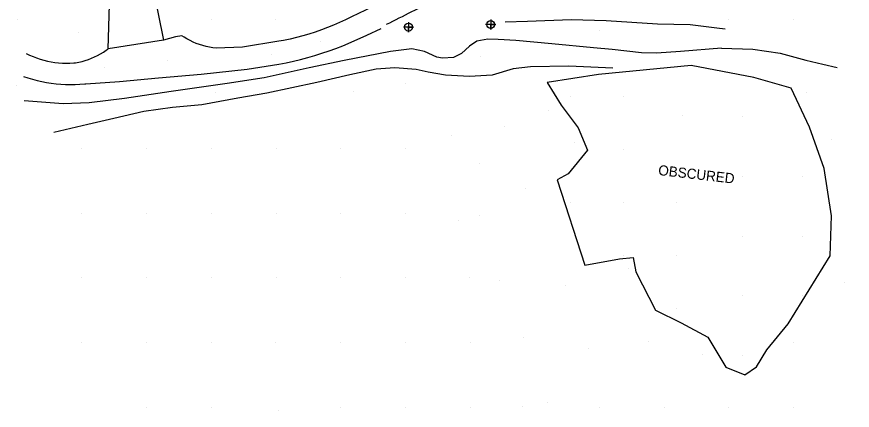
# Model space of a CAD drawing. Extents: x 524772 to 528246, y 273285 to 283088.
# Drawn here: x 526948.5 to 527074.5, y 276192.7 to 276252.1 of the extents above; entities that cross this region are included whole.
import ezdxf

# ---------------------------------------------------------------- set-up
doc = ezdxf.new("R2010")
doc.units = 0
for name, color, linetype in [('Exist DTM Regular Point CELL', 7, 'Continuous'), ('Exist Roads Soil', 7, 'Continuous'), ('PH Exist DTM Breakline', 7, 'Continuous'), ('PH Exist DTM Obscure Area', 7, 'Continuous'), ('PH Exist DTM Obscure Area Text', 7, 'Continuous'), ('PH Exist DTM Point', 7, 'Continuous')]:
    doc.layers.add(name, color=color, linetype=linetype)

# ---------------------------------------------------------------- blocks, each defined once
blk = doc.blocks.new('EXIST DTM REGULAR POINT')
at = {"layer": 'Exist DTM Regular Point CELL'}
blk.add_lwpolyline([(0, 0.00152), (0, -0.00152), (0, 0), (0.00152, 0), (-0.00152, 0)], dxfattribs=at)
blk.add_circle((0, 0), 0.00119, dxfattribs=at)

msp = doc.modelspace()

# ---------------------------------------------------------------- linework, layer by layer
at = {"layer": 'Exist Roads Soil'}
msp.add_spline([(527004.3, 276250.96), (527011.89, 276254.76), (527021.35, 276259.26), (527033.94, 276264.59), (527047.08, 276268.94), (527059.34, 276272.23), (527073.2, 276275.45), (527085.01, 276278.61), (527097.76, 276281.39), (527108, 276283.82), (527111.74, 276284.33), (527113.41, 276284.2), (527116.23, 276282.04), (527118.13, 276280.02)], degree=3, dxfattribs=at)
at = {"layer": 'PH Exist DTM Breakline'}
for points in [[(526969.04, 276256.57), (526970.63, 276248.58), (526962.29, 276247.27), (526962.49, 276253.93)], [(527002.18, 276253.59), (526998.98, 276252.07), (526998.09, 276251.64), (526997.2, 276251.22), (526996.29, 276250.83), (526995.38, 276250.46), (526994.46, 276250.12), (526993.53, 276249.79), (526992.59, 276249.49), (526991.64, 276249.22), (526990.69, 276248.96), (526989.73, 276248.73), (526988.77, 276248.53), (526988.05, 276248.39), (526982.57, 276247.53), (526978.59, 276247.37), (526978.08, 276247.43), (526977.57, 276247.51), (526977.07, 276247.62), (526976.57, 276247.75), (526976.08, 276247.9), (526975.59, 276248.08), (526975.11, 276248.28), (526974.65, 276248.5), (526974.19, 276248.75), (526973.75, 276249.01), (526973.42, 276249.23), (526972.47, 276249.05), (526970.63, 276248.58)], [(527022.18, 276251.31), (527025.54, 276251.42), (527032.13, 276251.69), (527037.41, 276251.52), (527045.17, 276251.03), (527050.08, 276250.92), (527054.11, 276250.42), (527055.36, 276250.29)], [(526949.52, 276243.1), (526950.2, 276242.87), (526950.89, 276242.66), (526951.59, 276242.47), (526952.3, 276242.32), (526953.01, 276242.18), (526953.72, 276242.07), (526954.44, 276241.98), (526955.16, 276241.92), (526955.88, 276241.88), (526956.6, 276241.86), (526957.32, 276241.87), (526958.05, 276241.9), (526958.77, 276241.96), (526958.92, 276241.98), (526964.02, 276242.33), (526969.9, 276242.87), (526976.31, 276243.41), (526983.27, 276244.21), (526988.04, 276244.92), (526989.13, 276245.14), (526990.23, 276245.38), (526991.32, 276245.65), (526992.4, 276245.94), (526993.48, 276246.25), (526994.55, 276246.58), (526995.61, 276246.94), (526996.66, 276247.33), (526997.71, 276247.73), (526998.07, 276247.88), (527001.31, 276249.33), (527003.5, 276250.34)], [(527054.81, 276247.36), (527048.61, 276246.83), (527044.99, 276246.59), (527042.74, 276246.65), (527038.3, 276247.13), (527035.48, 276247.42), (527029.23, 276247.99), (527023.8, 276248.53), (527021.11, 276248.67), (527019.58, 276248.72), (527017.91, 276248.41), (527016.8, 276247.64), (527015.57, 276246.55), (527014.36, 276245.96), (527012.72, 276245.85), (527011.85, 276246.01), (527010.03, 276246.83), (527008.1, 276247.24), (527004.88, 276246.87), (526997.9, 276245.5), (526992.61, 276244.38), (526985.81, 276242.89), (526980.23, 276242.02), (526971.81, 276240.83), (526964.79, 276239.74), (526959.46, 276239.12), (526955.52, 276238.95), (526949.63, 276239.43)], [(526949.95, 276246.56), (526950.46, 276246.31), (526950.99, 276246.08), (526951.52, 276245.88), (526952.06, 276245.7), (526952.6, 276245.54), (526953.16, 276245.4), (526953.71, 276245.29), (526954.28, 276245.2), (526954.84, 276245.14), (526955.41, 276245.1), (526955.98, 276245.08), (526956.55, 276245.09), (526957.12, 276245.13), (526957.38, 276245.15), (526957.88, 276245.24), (526958.37, 276245.35), (526958.86, 276245.49), (526959.34, 276245.64), (526959.81, 276245.83), (526960.27, 276246.03), (526960.72, 276246.25), (526961.17, 276246.5), (526961.6, 276246.77), (526962.01, 276247.06), (526962.29, 276247.27)], [(527054.81, 276247.36), (527059.5, 276247.19), (527063.65, 276246.6), (527067.53, 276245.55), (527070.08, 276244.93), (527072.22, 276244.46)], [(527038.4, 276244.35), (527031.78, 276244.64), (527026.01, 276244.55), (527023.37, 276244.25), (527020.21, 276243.3), (527016.79, 276243.1), (527013.18, 276243.3), (527010.54, 276243.73), (527008.75, 276244.14), (527005.54, 276244.38), (527002.72, 276244.17), (526998.74, 276243.31), (526993.77, 276242.18), (526986.25, 276240.57), (526981.84, 276239.8), (526976.45, 276238.8), (526972.02, 276238.38), (526967.69, 276237.78), (526963.18, 276236.72), (526959.24, 276235.84), (526954.1, 276234.64)]]:
    msp.add_lwpolyline(points, dxfattribs=at)
at = {"layer": 'PH Exist DTM Obscure Area'}
msp.add_lwpolyline([(527064.84, 276205.73), (527071.17, 276215.99), (527071.38, 276222.06), (527070.28, 276229.17), (527068.06, 276235.45), (527065.3, 276241.31), (527059.66, 276242.92), (527050.23, 276244.76), (527036.26, 276243.38), (527028.5, 276242.16), (527030.62, 276238.73), (527033.16, 276235.35), (527034.59, 276231.97), (527031.68, 276228.39), (527030.01, 276227.47), (527034.2, 276214.59), (527039.41, 276215.56), (527041.46, 276215.75), (527041.86, 276213.58), (527044.85, 276207.79), (527048.72, 276205.9), (527052.75, 276203.72), (527055.46, 276199.2), (527058.34, 276198.03), (527060.1, 276199.24), (527061.62, 276201.8), (527064.84, 276205.73)], dxfattribs=at)
at = {"layer": 'PH Exist DTM Point'}
for p, q in [((526948.61, 276251.7), (526948.61, 276251.7)), ((526977.85, 276251.69), (526977.85, 276251.69)), ((526987.61, 276251.67), (526987.61, 276251.67)), ((527055.92, 276251.69), (527055.92, 276251.69)), ((527065.63, 276251.71), (527065.63, 276251.71)), ((527036.36, 276250.08), (527036.36, 276250.08)), ((526957.88, 276249.66), (526957.88, 276249.66)), ((526994.33, 276248.36), (526994.33, 276248.36)), ((526986.88, 276246.43), (526986.88, 276246.43)), ((526971.18, 276245.5), (526971.18, 276245.5)), ((527018.52, 276246.13), (527018.52, 276246.13)), ((526961.75, 276244.48), (526961.75, 276244.48)), ((526948.51, 276241.77), (526948.51, 276241.77)), ((527007.13, 276241.95), (527007.13, 276241.95)), ((526978.43, 276240.61), (526978.43, 276240.61)), ((526999.27, 276240.78), (526999.27, 276240.78)), ((527032, 276240), (527032, 276240)), ((527040, 276240), (527040, 276240)), ((527067.69, 276240.72), (527067.69, 276240.72)), ((527028.72, 276237.93), (527028.72, 276237.93)), ((527048.98, 276237.12), (527048.98, 276237.12)), ((527058, 276237.01), (527058, 276237.01)), ((527022.02, 276235.49), (527022.02, 276235.49)), ((527014.05, 276234.22), (527014.05, 276234.22)), ((527032.6, 276233.19), (527032.6, 276233.19)), ((527071.44, 276233.62), (527071.44, 276233.62)), ((526958.36, 276232.19), (526958.36, 276232.19)), ((526968.11, 276232.19), (526968.11, 276232.19)), ((526977.87, 276232.19), (526977.87, 276232.19)), ((526987.62, 276232.19), (526987.62, 276232.19)), ((526997.38, 276232.19), (526997.38, 276232.19)), ((527007.13, 276232.19), (527007.13, 276232.19)), ((527040, 276232), (527040, 276232)), ((527018.35, 276229.99), (527018.35, 276229.99)), ((527049, 276228), (527049, 276228)), ((527058, 276228), (527058, 276228)), ((527067, 276228), (527067, 276228)), ((527025.2, 276226.11), (527025.2, 276226.11)), ((527032, 276224), (527032, 276224)), ((527040, 276224), (527040, 276224)), ((527048, 276224), (527048, 276224)), ((526958.36, 276222.44), (526958.36, 276222.44)), ((526968.11, 276222.44), (526968.11, 276222.44)), ((526977.87, 276222.44), (526977.87, 276222.44)), ((526987.63, 276222.42), (526987.63, 276222.42)), ((526997.36, 276222.41), (526997.36, 276222.41)), ((527007.13, 276222.44), (527007.13, 276222.44)), ((527015.08, 276221.3), (527015.08, 276221.3)), ((527018.28, 276222.09), (527018.28, 276222.09)), ((527058, 276219), (527058, 276219)), ((527067, 276219), (527067, 276219)), ((527040, 276216), (527040, 276216)), ((527048, 276216), (527048, 276216)), ((527040.7, 276214.05), (527040.7, 276214.05)), ((526958.36, 276212.69), (526958.36, 276212.69)), ((526968.11, 276212.69), (526968.11, 276212.69)), ((526977.87, 276212.69), (526977.87, 276212.69)), ((526987.62, 276212.7), (526987.62, 276212.7)), ((526997.38, 276212.69), (526997.38, 276212.69)), ((527007.13, 276212.69), (527007.13, 276212.69)), ((527016.84, 276212.67), (527016.84, 276212.67)), ((527021.25, 276212.36), (527021.25, 276212.36)), ((527031.34, 276211.59), (527031.34, 276211.59)), ((527073.33, 276211.94), (527073.33, 276211.94)), ((527058, 276210), (527058, 276210)), ((527067, 276210), (527067, 276210)), ((527048, 276208), (527048, 276208)), ((527025.01, 276203.62), (527025.01, 276203.62)), ((526958.36, 276202.93), (526958.36, 276202.93)), ((526968.11, 276202.93), (526968.11, 276202.93)), ((526977.87, 276202.93), (526977.87, 276202.93)), ((526987.58, 276202.92), (526987.58, 276202.92)), ((526997.35, 276202.94), (526997.35, 276202.94)), ((527007.13, 276202.93), (527007.13, 276202.93)), ((527016.88, 276202.93), (527016.88, 276202.93)), ((527043.86, 276203.14), (527043.86, 276203.14)), ((527065.65, 276202.93), (527065.65, 276202.93)), ((527034.74, 276201.99), (527034.74, 276201.99)), ((527052, 276201.1), (527052, 276201.1)), ((527058, 276201), (527058, 276201)), ((527028.56, 276193.91), (527028.56, 276193.91)), ((526968.11, 276193.18), (526968.11, 276193.18)), ((526977.87, 276193.18), (526977.87, 276193.18)), ((526987.93, 276192.69), (526987.93, 276192.69)), ((526997.38, 276193.18), (526997.38, 276193.18)), ((527007.13, 276193.18), (527007.13, 276193.18)), ((527016.88, 276193.18), (527016.88, 276193.18)), ((527024.81, 276193.27), (527024.81, 276193.27)), ((527036.37, 276193.17), (527036.37, 276193.17)), ((527046.14, 276193.18), (527046.14, 276193.18)), ((527055.9, 276193.18), (527055.9, 276193.18)), ((527065.65, 276193.18), (527065.65, 276193.18))]:
    msp.add_line(p, q, dxfattribs=at)

# ---------------------------------------------------------------- block references
at = {"layer": 'Exist DTM Regular Point CELL', "xscale": 500, "yscale": 500}
for p in [(527007.6, 276250.54), (527019.99, 276250.93)]:
    msp.add_blockref('EXIST DTM REGULAR POINT', p, dxfattribs=at)

# ---------------------------------------------------------------- texts
at = {"layer": 'PH Exist DTM Obscure Area Text'}
msp.add_text('OBSCURED', height=1.524, rotation=353.4693, dxfattribs=at).set_placement((527045.2, 276228.22))

doc.saveas('drawing.dxf')
